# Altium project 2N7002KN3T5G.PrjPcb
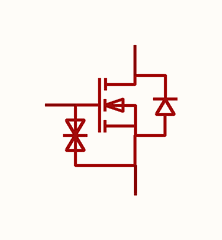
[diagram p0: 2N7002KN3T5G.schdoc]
1 sheet, 1 parts. Net scope: global (net labels, ports and power ports of the same name join across sheets).

## Sheet 2N7002KN3T5G.schdoc
size 127 x 101 mm

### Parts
Q?  2n7002kn3t5g  [SOT-883-3_L1.0-W0.6-BR]  (value not drawn)

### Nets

Not connected (* = marked no-connect by the designer): Q? 1(G) 2(S) 3(D)

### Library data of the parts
Q? = 2n7002kn3t5g: 数量:1个N沟道;漏源电压(Vdss):60V;连续漏极电流(Id):300mA;导通电阻(RDS(on)):1.7Ω@10V;耗散功率(Pd):156mW;阈值电压(Vgs(th)):2V;; Manufacturer: MSKSEMI(美森科); AddInBom: yes; ModelId: d7644a22f86a4c7dbbf73274f076c690; ModelName: SOT-883-3_L1.0-W0.6-H0.5-BR; ModelTransform: 40.1574,24.4094,0,0,0,0,0,0,0; Number: 1个N沟道; Drain to Source Voltage: 60V; Current - Continuous Drain(Id): 300mA; Pd - Power Dissipation: 156mW; Gate Threshold Voltage (Vgs(th)): 2V; Gate Charge(Qg): 3.5nC@10V; Input Capacitance(Ciss): 15pF; Reverse Transfer Capacitance (Crss@Vds): 1pF; Output Capacitance(Coss): 2pF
